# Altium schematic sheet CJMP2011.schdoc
size 127 x 101 mm
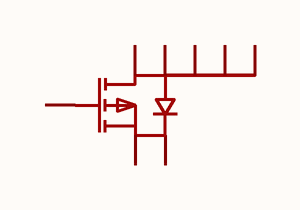
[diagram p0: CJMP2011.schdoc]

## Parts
Q?  cjmp2011  [PDFN-6_L2.0-W2.0-P0.65-BL-EP1.2]  (value not drawn)

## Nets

Not connected (* = marked no-connect by the designer): Q? 1(D) 2(D) 3(G) 4(S) 5(D) 6(D) 7(D) 8(S)

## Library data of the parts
Q? = cjmp2011: 数量:1个P沟道;漏源电压(Vdss):20V;连续漏极电流(Id):11A;导通电阻(RDS(on)):15mΩ@4.5V；22mΩ@2.5V;耗散功率(Pd):750mW;阈值电压(Vgs(th)):1.2V;; Manufacturer: CJ(江苏长电/长晶); AddInBom: yes; ModelId: e1f45bfebba24b46824beeab666fc30b; ModelTransform: 78.74,79.527,0,0,0,0,0,0,0; Number: 1个P沟道; Drain to Source Voltage: 20V; Current - Continuous Drain(Id): 11A; Pd - Power Dissipation: 750mW; Gate Threshold Voltage (Vgs(th)): 1.2V; Gate Charge(Qg): 35nC; Input Capacitance(Ciss): 2.7nF; Reverse Transfer Capacitance (Crss@Vds): 590pF; Type: P沟道; Output Capacitance(Coss): 680pF; Vgs: ±12V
